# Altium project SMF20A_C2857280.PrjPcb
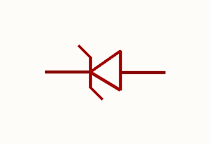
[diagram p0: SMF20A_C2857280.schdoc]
1 sheet, 1 parts. Net scope: global (net labels, ports and power ports of the same name join across sheets).

## Sheet SMF20A_C2857280.schdoc
size 127 x 101 mm

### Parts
D?  smf20a_c2857280  [SOD-123FL_L2.8-W1.8-LS3.6-RD]  (value not drawn)

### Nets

Not connected (* = marked no-connect by the designer): D? 1(C) 2(A)

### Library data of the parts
D? = smf20a_c2857280: 极性:单向;反向截止电压(Vrwm):20V;钳位电压:32.4V;峰值脉冲电流(Ipp):6.2A;峰值脉冲功率(Ppp):200W@10/1000us;击穿电压(VBR):22.2V;; Manufacturer: JSMSEMI(杰盛微); ManufacturerPart: SMF20A; AddInBom: yes; ModelId: 9a6bf0a398604d2998ad78800a7c8ef9; ModelTransform: 141.732,70.866,0,0,0,0,0,0,0; Polarity: 单向; Reverse Stand-Off Voltage (Vrwm): 20V; Clamping Voltage: 32.4V; Peak Pulse Current (Ipp): 6.2A; Voltage - Breakdown: 22.2V; Reverse Leakage Current (Ir): 1uA; Number of Channels: 单路; Type: TVS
